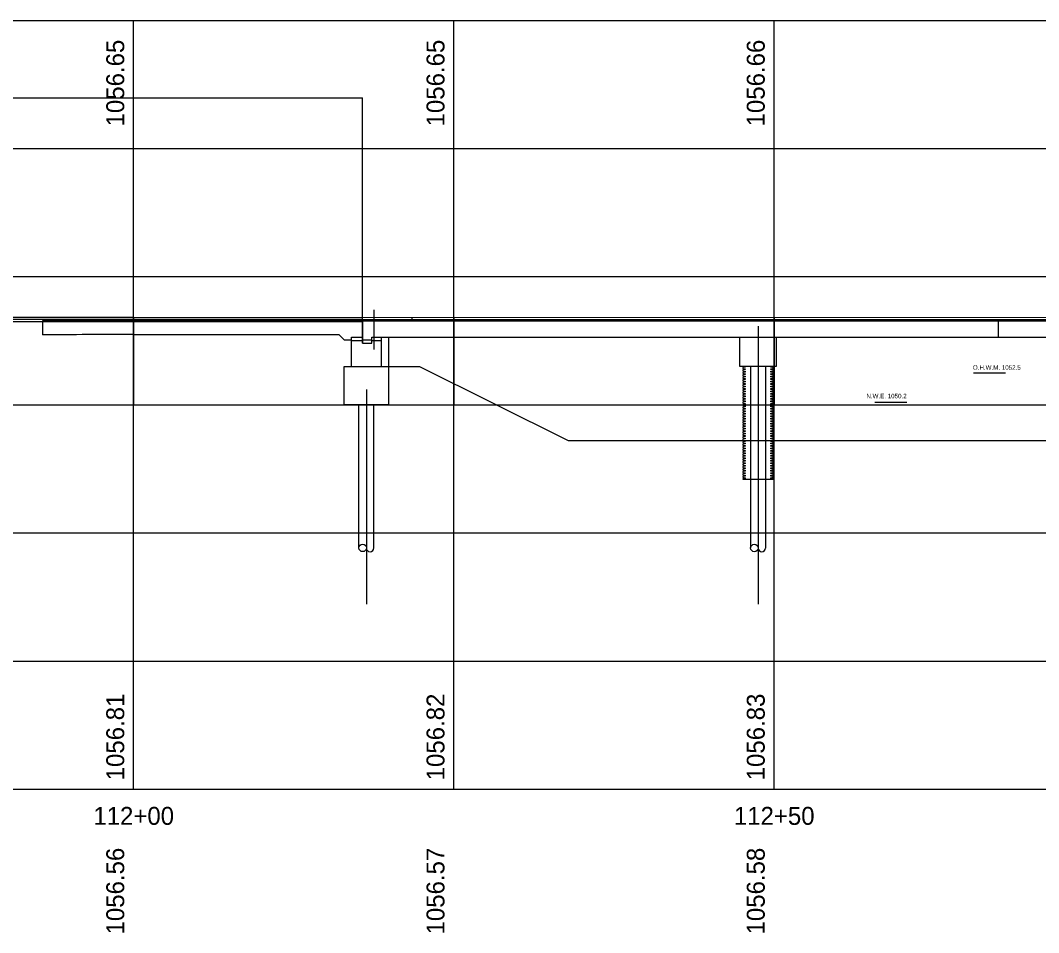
# Model space of a CAD drawing. Extents: x -2063 to 2068, y 79 to 1202.
# Drawn here: x -1678.2 to -1598.7, y 250.8 to 322 of the extents above; entities that cross this region are included whole.
import ezdxf

# ---------------------------------------------------------------- set-up
doc = ezdxf.new("R2010")
doc.units = 0
for name, color, linetype in [('BR_P_Gen_Approach_Slab', 7, 'Continuous'), ('BR_P_Gen_Joint_Filler', 7, 'Continuous'), ('BR_P_Slab_Object', 7, 'Continuous'), ('BR_X_Brg_Centerline', 7, 'Continuous'), ('BR_X_Gen_Approach_Slab', 7, 'Continuous'), ('BR_X_Slab_Object', 7, 'Continuous'), ('BR_X_Sub_Deep_Centerline', 7, 'Continuous'), ('BR_X_Sub_Deep_Object', 7, 'Continuous'), ('BR_X_Sub_Object', 7, 'Continuous'), ('PF_X_Ground_Line', 7, 'Continuous'), ('SC_Scratch1', 7, 'Continuous'), ('SC_Scratch2', 7, 'Continuous'), ('SC_Scratch3', 7, 'Continuous'), ('XS_P_Pavt_Surface', 7, 'Continuous')]:
    doc.layers.add(name, color=color, linetype=linetype)

msp = doc.modelspace()

# ---------------------------------------------------------------- linework, layer by layer
at = {"layer": 'BR_P_Gen_Approach_Slab'}
msp.add_line((-1676.447, 298.477), (-1651.447, 298.471), dxfattribs=at)
at = {"layer": 'BR_P_Gen_Joint_Filler'}
msp.add_lwpolyline([(-1651.53, 298.617), (-1651.447, 298.617), (-1651.447, 298.45), (-1651.53, 298.45)], close=True, dxfattribs=at)
at = {"layer": 'BR_P_Slab_Object'}
msp.add_line((-1651.447, 298.471), (-1651.447, 298.617), dxfattribs=at)
for points in [[(-1651.447, 298.617), (-1619.327, 298.63), (-1569.327, 298.61)], [(-1569.327, 298.464), (-1619.327, 298.484), (-1651.447, 298.471)]]:
    msp.add_lwpolyline(points, dxfattribs=at)
at = {"layer": 'BR_X_Brg_Centerline'}
for p, q in [((-1650.581, 299.375), (-1650.581, 296.271)), ((-1620.577, 298.095), (-1620.577, 276.394))]:
    msp.add_line(p, q, dxfattribs=at)
at = {"layer": 'BR_X_Gen_Approach_Slab'}
for p, q in [((-1676.447, 298.519), (-1676.447, 297.435)), ((-1651.447, 298.533), (-1669.327, 298.526)), ((-1669.327, 297.443), (-1653.305, 297.449)), ((-1653.305, 297.449), (-1652.89, 297.034)), ((-1652.89, 297.034), (-1652.313, 297.034))]:
    msp.add_line(p, q, dxfattribs=at)
for centre in [(-1606.827, -62201.629), (-1606.827, -62202.712)]:
    msp.add_arc(centre, 62500.186, 90.05729577, 90.06382289, dxfattribs=at)
at = {"layer": 'BR_X_Slab_Object'}
msp.add_line((-1651.447, 298.533), (-1651.447, 297.243), dxfattribs=at)
for points in [[(-1569.327, 298.526), (-1619.327, 298.546), (-1651.447, 298.533)], [(-1649.426, 297.243), (-1619.327, 297.255), (-1569.327, 297.235)]]:
    msp.add_lwpolyline(points, dxfattribs=at)
at = {"layer": 'BR_X_Sub_Deep_Centerline'}
msp.add_line((-1651.158, 293.158), (-1651.158, 276.394), dxfattribs=at)
at = {"layer": 'BR_X_Sub_Deep_Object'}
for p, q in [((-1621.16, 294.983), (-1621.16, 280.788)), ((-1619.993, 294.983), (-1619.993, 280.788)), ((-1651.738, 280.794), (-1651.738, 291.966)), ((-1650.571, 280.794), (-1650.571, 291.966))]:
    msp.add_line(p, q, dxfattribs=at)
msp.add_lwpolyline([(-1621.655, 294.983), (-1621.577, 294.97), (-1621.577, 294.907), (-1621.76, 294.876), (-1621.76, 294.808), (-1621.577, 294.776), (-1621.577, 294.714), (-1621.76, 294.683), (-1621.76, 294.614), (-1621.577, 294.583), (-1621.577, 294.523), (-1621.76, 294.492), (-1621.76, 294.423), (-1621.577, 294.392), (-1621.577, 294.33), (-1621.76, 294.298), (-1621.76, 294.23), (-1621.577, 294.199), (-1621.577, 294.136), (-1621.76, 294.105), (-1621.76, 294.037), (-1621.577, 294.006), (-1621.577, 293.943), (-1621.76, 293.912), (-1621.76, 293.844), (-1621.577, 293.812), (-1621.577, 293.75), (-1621.76, 293.718), (-1621.76, 293.65), (-1621.577, 293.619), (-1621.577, 293.556), (-1621.76, 293.525), (-1621.76, 293.457), (-1621.577, 293.426), (-1621.577, 293.363), (-1621.76, 293.332), (-1621.76, 293.264), (-1621.577, 293.232), (-1621.577, 293.17), (-1621.76, 293.139), (-1621.76, 293.07), (-1621.577, 293.039), (-1621.577, 292.977), (-1621.76, 292.945), (-1621.76, 292.877), (-1621.577, 292.846), (-1621.577, 292.783), (-1621.76, 292.752), (-1621.76, 292.684), (-1621.577, 292.652), (-1621.577, 292.59), (-1621.76, 292.559), (-1621.76, 292.49), (-1621.577, 292.459), (-1621.577, 292.397), (-1621.76, 292.365), (-1621.76, 292.297), (-1621.577, 292.266), (-1621.577, 292.203), (-1621.76, 292.172), (-1621.76, 292.104), (-1621.577, 292.073), (-1621.577, 292.01), (-1621.76, 291.979), (-1621.76, 291.911), (-1621.577, 291.879), (-1621.577, 291.817), (-1621.76, 291.785), (-1621.76, 291.717), (-1621.577, 291.686), (-1621.577, 291.623), (-1621.76, 291.592), (-1621.76, 291.524), (-1621.577, 291.493), (-1621.577, 291.43), (-1621.76, 291.399), (-1621.76, 291.331), (-1621.577, 291.299), (-1621.577, 291.237), (-1621.76, 291.206), (-1621.76, 291.137), (-1621.577, 291.106), (-1621.577, 291.044), (-1621.76, 291.012), (-1621.76, 290.944), (-1621.577, 290.913), (-1621.577, 290.85), (-1621.76, 290.819), (-1621.76, 290.751), (-1621.577, 290.719), (-1621.577, 290.657), (-1621.76, 290.626), (-1621.76, 290.557), (-1621.577, 290.526), (-1621.577, 290.464), (-1621.76, 290.432), (-1621.76, 290.364), (-1621.577, 290.333), (-1621.577, 290.27), (-1621.76, 290.239), (-1621.76, 290.171), (-1621.577, 290.14), (-1621.577, 290.077), (-1621.76, 290.046), (-1621.76, 289.978), (-1621.577, 289.946), (-1621.577, 289.884), (-1621.76, 289.852), (-1621.76, 289.784), (-1621.577, 289.753), (-1621.577, 289.69), (-1621.76, 289.659), (-1621.76, 289.591), (-1621.577, 289.56), (-1621.577, 289.497), (-1621.76, 289.466), (-1621.76, 289.398), (-1621.577, 289.366), (-1621.577, 289.304), (-1621.76, 289.273), (-1621.76, 289.204), (-1621.577, 289.173), (-1621.577, 289.111), (-1621.76, 289.079), (-1621.76, 289.011), (-1621.577, 288.98), (-1621.577, 288.917), (-1621.76, 288.886), (-1621.76, 288.818), (-1621.577, 288.786), (-1621.577, 288.724), (-1621.76, 288.693), (-1621.76, 288.624), (-1621.577, 288.593), (-1621.577, 288.531), (-1621.76, 288.499), (-1621.76, 288.431), (-1621.577, 288.4), (-1621.577, 288.337), (-1621.76, 288.306), (-1621.76, 288.238), (-1621.577, 288.207), (-1621.577, 288.144), (-1621.76, 288.113), (-1621.76, 288.045), (-1621.577, 288.013), (-1621.577, 287.951), (-1621.76, 287.92), (-1621.76, 287.851), (-1621.577, 287.82), (-1621.577, 287.757), (-1621.76, 287.726), (-1621.76, 287.658), (-1621.577, 287.627), (-1621.577, 287.564), (-1621.76, 287.533), (-1621.76, 287.465), (-1621.577, 287.433), (-1621.577, 287.371), (-1621.76, 287.34), (-1621.76, 287.271), (-1621.577, 287.24), (-1621.577, 287.178), (-1621.76, 287.146), (-1621.76, 287.078), (-1621.577, 287.047), (-1621.577, 286.984), (-1621.76, 286.953), (-1621.76, 286.885), (-1621.577, 286.853), (-1621.577, 286.791), (-1621.76, 286.76), (-1621.76, 286.691), (-1621.577, 286.66), (-1621.577, 286.598), (-1621.76, 286.566), (-1621.76, 286.498), (-1621.577, 286.467), (-1621.577, 286.404), (-1621.76, 286.373), (-1621.76, 286.305), (-1621.577, 286.274), (-1621.577, 286.211), (-1621.76, 286.18), (-1621.76, 286.166), (-1619.393, 286.166), (-1619.393, 286.18), (-1619.577, 286.211), (-1619.577, 286.274), (-1619.393, 286.305), (-1619.393, 286.373), (-1619.577, 286.404), (-1619.577, 286.467), (-1619.393, 286.498), (-1619.393, 286.566), (-1619.577, 286.598), (-1619.577, 286.66), (-1619.393, 286.691), (-1619.393, 286.76), (-1619.577, 286.791), (-1619.577, 286.853), (-1619.393, 286.885), (-1619.393, 286.953), (-1619.577, 286.984), (-1619.577, 287.047), (-1619.393, 287.078), (-1619.393, 287.146), (-1619.577, 287.178), (-1619.577, 287.24), (-1619.393, 287.271), (-1619.393, 287.34), (-1619.577, 287.371), (-1619.577, 287.433), (-1619.393, 287.465), (-1619.393, 287.533), (-1619.577, 287.564), (-1619.577, 287.627), (-1619.393, 287.658), (-1619.393, 287.726), (-1619.577, 287.757), (-1619.577, 287.82), (-1619.393, 287.851), (-1619.393, 287.92), (-1619.577, 287.951), (-1619.577, 288.013), (-1619.393, 288.045), (-1619.393, 288.113), (-1619.577, 288.144), (-1619.577, 288.207), (-1619.393, 288.238), (-1619.393, 288.306), (-1619.577, 288.337), (-1619.577, 288.4), (-1619.393, 288.431), (-1619.393, 288.499), (-1619.577, 288.531), (-1619.577, 288.593), (-1619.393, 288.624), (-1619.393, 288.693), (-1619.577, 288.724), (-1619.577, 288.786), (-1619.393, 288.818), (-1619.393, 288.886), (-1619.577, 288.917), (-1619.577, 288.98), (-1619.393, 289.011), (-1619.393, 289.079), (-1619.577, 289.111), (-1619.577, 289.173), (-1619.393, 289.204), (-1619.393, 289.273), (-1619.577, 289.304), (-1619.577, 289.366), (-1619.393, 289.398), (-1619.393, 289.466), (-1619.577, 289.497), (-1619.577, 289.56), (-1619.393, 289.591), (-1619.393, 289.659), (-1619.577, 289.69), (-1619.577, 289.753), (-1619.393, 289.784), (-1619.393, 289.852), (-1619.577, 289.884), (-1619.577, 289.946), (-1619.393, 289.978), (-1619.393, 290.046), (-1619.577, 290.077), (-1619.577, 290.14), (-1619.393, 290.171), (-1619.393, 290.239), (-1619.577, 290.27), (-1619.577, 290.333), (-1619.393, 290.364), (-1619.393, 290.432), (-1619.577, 290.464), (-1619.577, 290.526), (-1619.393, 290.557), (-1619.393, 290.626), (-1619.577, 290.657), (-1619.577, 290.719), (-1619.393, 290.751), (-1619.393, 290.819), (-1619.577, 290.85), (-1619.577, 290.913), (-1619.393, 290.944), (-1619.393, 291.012), (-1619.577, 291.044), (-1619.577, 291.106), (-1619.393, 291.137), (-1619.393, 291.206), (-1619.577, 291.237), (-1619.577, 291.299), (-1619.393, 291.331), (-1619.393, 291.399), (-1619.577, 291.43), (-1619.577, 291.493), (-1619.393, 291.524), (-1619.393, 291.592), (-1619.577, 291.623), (-1619.577, 291.686), (-1619.393, 291.717), (-1619.393, 291.785), (-1619.577, 291.817), (-1619.577, 291.879), (-1619.393, 291.911), (-1619.393, 291.979), (-1619.577, 292.01), (-1619.577, 292.073), (-1619.393, 292.104), (-1619.393, 292.172), (-1619.577, 292.203), (-1619.577, 292.266), (-1619.393, 292.297), (-1619.393, 292.365), (-1619.577, 292.397), (-1619.577, 292.459), (-1619.393, 292.49), (-1619.393, 292.559), (-1619.577, 292.59), (-1619.577, 292.652), (-1619.393, 292.684), (-1619.393, 292.752), (-1619.577, 292.783), (-1619.577, 292.846), (-1619.393, 292.877), (-1619.393, 292.945), (-1619.577, 292.977), (-1619.577, 293.039), (-1619.393, 293.07), (-1619.393, 293.139), (-1619.577, 293.17), (-1619.577, 293.232), (-1619.393, 293.264), (-1619.393, 293.332), (-1619.577, 293.363), (-1619.577, 293.426), (-1619.393, 293.457), (-1619.393, 293.525), (-1619.577, 293.556), (-1619.577, 293.619), (-1619.393, 293.65), (-1619.393, 293.718), (-1619.577, 293.75), (-1619.577, 293.812), (-1619.393, 293.844), (-1619.393, 293.912), (-1619.577, 293.943), (-1619.577, 294.006), (-1619.393, 294.037), (-1619.393, 294.105), (-1619.577, 294.136), (-1619.577, 294.199), (-1619.393, 294.23), (-1619.393, 294.298), (-1619.577, 294.33), (-1619.577, 294.392), (-1619.393, 294.423), (-1619.393, 294.492), (-1619.577, 294.523), (-1619.577, 294.583), (-1619.393, 294.614), (-1619.393, 294.683), (-1619.577, 294.714), (-1619.577, 294.776), (-1619.393, 294.808), (-1619.393, 294.876), (-1619.577, 294.907), (-1619.577, 294.97), (-1619.499, 294.983)], dxfattribs=at)
for centre, radius in [((-1651.448, 280.794), 0.29), ((-1620.868, 280.788), 0.292)]:
    msp.add_circle(centre, radius, dxfattribs=at)
for centre, radius in [((-1650.865, 280.794), 0.293), ((-1620.285, 280.788), 0.292)]:
    msp.add_arc(centre, radius, 180, 0, dxfattribs=at)
at = {"layer": 'BR_X_Sub_Object'}
for p, q in [((-1652.313, 294.966), (-1652.313, 297.242)), ((-1652.313, 297.242), (-1651.447, 297.242)), ((-1651.447, 297.242), (-1651.447, 297.034)), ((-1651.447, 297.034), (-1650.725, 297.034)), ((-1650.003, 297.242), (-1649.426, 297.242)), ((-1650.003, 297.242), (-1650.003, 294.966)), ((-1649.426, 297.242), (-1649.426, 294.966)), ((-1652.89, 291.966), (-1652.89, 294.966)), ((-1652.89, 294.966), (-1649.426, 294.966)), ((-1649.426, 294.966), (-1649.426, 291.966)), ((-1649.426, 291.966), (-1652.89, 291.966))]:
    msp.add_line(p, q, dxfattribs=at)
for points in [[(-1650.725, 297.034), (-1650.725, 297.242), (-1650.003, 297.242)], [(-1622.02, 297.254), (-1622.02, 294.983), (-1619.133, 294.983), (-1619.133, 297.255)]]:
    msp.add_lwpolyline(points, dxfattribs=at)
at = {"layer": 'PF_X_Ground_Line'}
for p, q in [((-1649.426, 294.966), (-1647.003, 294.966)), ((-1647.003, 294.966), (-1635.403, 289.166)), ((-1635.403, 289.166), (-1568.25, 289.166))]:
    msp.add_line(p, q, dxfattribs=at)
msp.add_lwpolyline([(-1669.327, 298.776), (-1619.327, 298.796), (-1569.327, 298.776)], dxfattribs=at)
for centre, radius, start, end in [((-1606.827, -62201.379), 62500.186, 90.06382289, 90.10313231), ((-1667.159, -5120.128), 5418.905, 90.022918, 90.0982)]:
    msp.add_arc(centre, radius, start, end, dxfattribs=at)
at = {"layer": 'SC_Scratch1'}
for p, q in [((-1969.327, 321.966), (-1244.327, 321.966)), ((-1669.327, 261.966), (-1669.327, 321.966)), ((-1644.327, 261.966), (-1644.327, 321.966)), ((-1619.327, 261.966), (-1619.327, 321.966)), ((-1969.327, 311.966), (-1244.327, 311.966)), ((-1969.327, 301.966), (-1244.327, 301.966)), ((-1647.577, 298.535), (-1647.577, 298.785)), ((-1969.327, 291.966), (-1244.327, 291.966)), ((-1969.327, 281.966), (-1244.327, 281.966)), ((-1969.327, 271.966), (-1244.327, 271.966)), ((-1969.327, 261.966), (-1244.327, 261.966))]:
    msp.add_line(p, q, dxfattribs=at)
msp.add_lwpolyline([(-1652.313, 296.971), (-1651.447, 296.971), (-1651.447, 296.763), (-1650.725, 296.763), (-1650.725, 296.971), (-1650.003, 296.971)], dxfattribs=at)
at = {"layer": 'SC_Scratch2'}
for p, q in [((-1669.327, 298.621), (-1669.327, 291.966)), ((-1644.327, 298.62), (-1644.327, 291.966)), ((-1619.327, 298.63), (-1619.327, 291.966))]:
    msp.add_line(p, q, dxfattribs=at)
at = {"layer": 'SC_Scratch3'}
for p, q in [((-1751.447, 315.917), (-1651.447, 315.917)), ((-1651.447, 296.763), (-1651.447, 315.917)), ((-1669.327, 298.776), (-1669.327, 291.966)), ((-1644.327, 298.786), (-1644.327, 291.966)), ((-1619.327, 298.796), (-1619.327, 291.966)), ((-1601.826, 298.539), (-1601.826, 297.248)), ((-1603.777, 294.467), (-1601.277, 294.467)), ((-1611.477, 292.172), (-1608.977, 292.172))]:
    msp.add_line(p, q, dxfattribs=at)
at = {"layer": 'XS_P_Pavt_Surface'}
for p, q in [((-1651.447, 298.617), (-1751.447, 298.64)), ((-1751.447, 298.494), (-1676.447, 298.477))]:
    msp.add_line(p, q, dxfattribs=at)

# ---------------------------------------------------------------- texts
at = {"layer": 'SC_Scratch1'}
for s, p in [('1056.65', (-1670.06, 313.69)), ('1056.65', (-1645.06, 313.69)), ('1056.66', (-1620.06, 313.69)), ('1056.81', (-1670.06, 262.658)), ('1056.82', (-1645.06, 262.658)), ('1056.83', (-1620.06, 262.658)), ('1056.56', (-1670.06, 250.63)), ('1056.57', (-1645.06, 250.63)), ('1056.58', (-1620.06, 250.63))]:
    msp.add_text(s, height=1.4, rotation=90, dxfattribs=at).set_placement(p)
for s, p in [('112+00', (-1672.469, 259.185)), ('112+50', (-1622.469, 259.185))]:
    msp.add_text(s, height=1.4, dxfattribs=at).set_placement(p)
at = {"layer": 'SC_Scratch3'}
for s, p in [('O.H.W.M. 1052.5', (-1603.81, 294.704)), ('N.W.E. 1050.2', (-1612.124, 292.474))]:
    msp.add_text(s, height=0.35, dxfattribs=at).set_placement(p)

doc.saveas('drawing.dxf')
